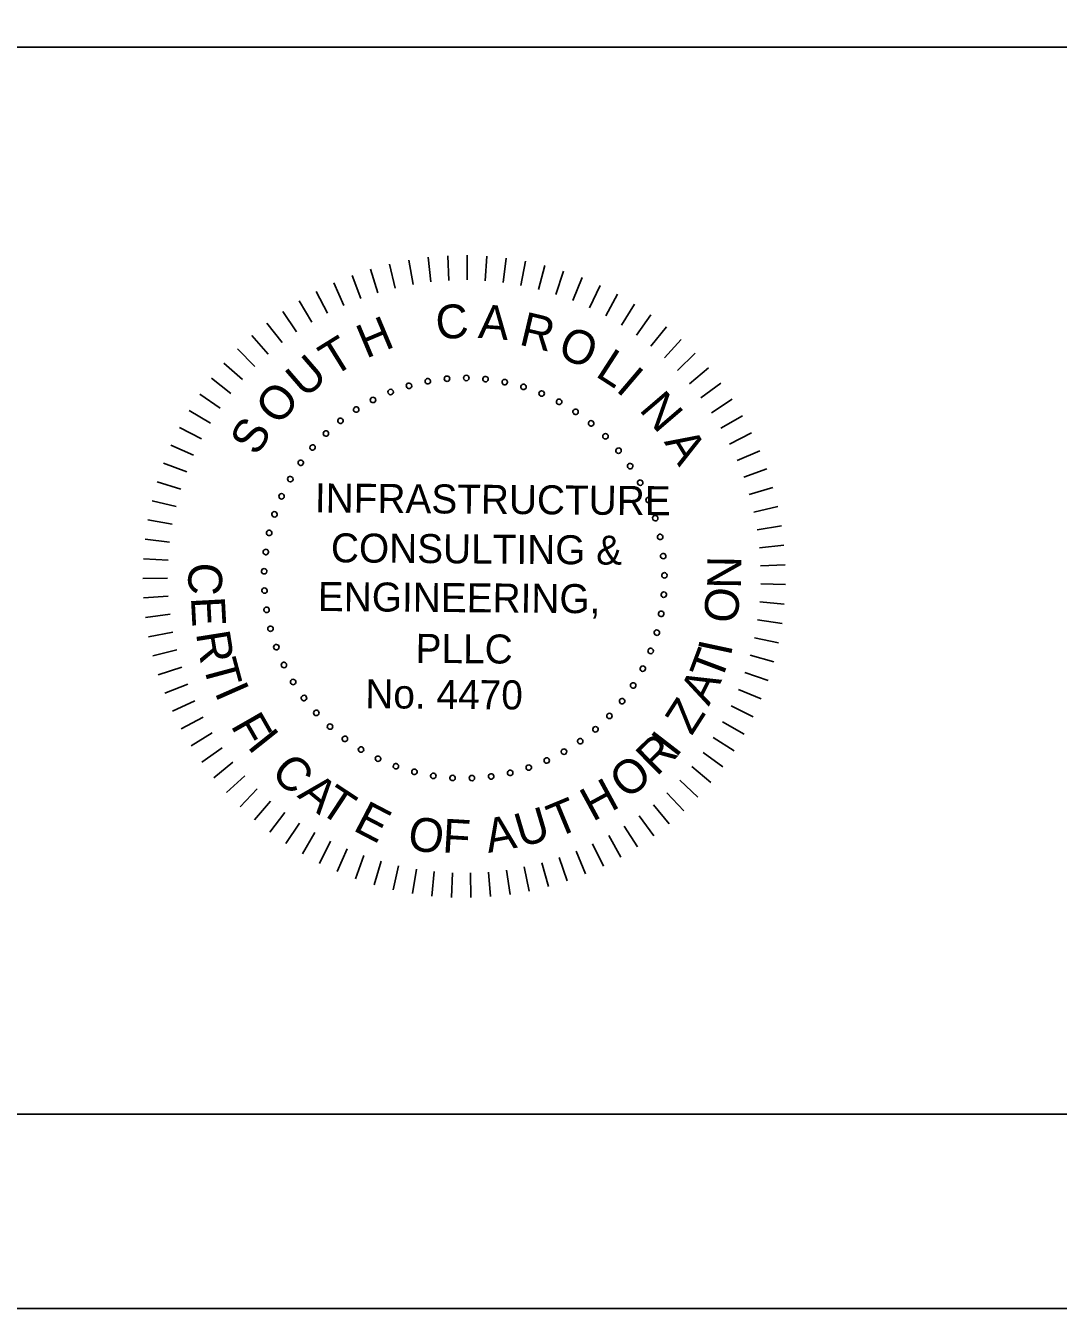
# Model space of a CAD drawing. Extents: x -125.5 to -89.4, y -5.1 to 16.9.
# Drawn here: x -100.33 to -97.669, y -5.066 to -1.761 of the extents above; entities that cross this region are included whole.
import ezdxf

# ---------------------------------------------------------------- set-up
doc = ezdxf.new("R2010")
doc.units = 0
for name, color, linetype in [('BR_BORDER LINES', 7, 'Continuous'), ('BR_TEXT', 7, 'Continuous'), ('Level 31', 7, 'Continuous')]:
    doc.layers.add(name, color=color, linetype=linetype)

msp = doc.modelspace()

# ---------------------------------------------------------------- linework, layer by layer
at = {"layer": 'BR_BORDER LINES'}
for p, q in [((-102.8989, -1.8161), (-97.5337, -1.8161)), ((-123.6994, -4.5662), (-90.0334, -4.5662))]:
    msp.add_line(p, q, dxfattribs=at)
at = {"layer": 'BR_TEXT'}
for p, q in [((-99.3925, -2.3754), (-99.3776, -2.4373)), ((-99.343, -2.3651), (-99.332, -2.4278)), ((-99.2931, -2.3579), (-99.2858, -2.4212)), ((-99.2427, -2.3538), (-99.2394, -2.4174)), ((-99.1923, -2.3527), (-99.1928, -2.4164)), ((-99.1418, -2.3548), (-99.1462, -2.4183)), ((-99.0916, -2.3599), (-99.0999, -2.423)), ((-99.0418, -2.368), (-99.0539, -2.4305)), ((-98.9925, -2.3792), (-99.0084, -2.4408)), ((-99.489, -2.4048), (-99.4667, -2.4644)), ((-99.4412, -2.3886), (-99.4226, -2.4495)), ((-98.9441, -2.3933), (-98.9637, -2.4539)), ((-98.8966, -2.4104), (-98.9199, -2.4696)), ((-99.5813, -2.4457), (-99.5519, -2.5022)), ((-99.5358, -2.4238), (-99.5099, -2.482)), ((-98.8502, -2.4303), (-98.877, -2.488)), ((-99.6253, -2.4703), (-99.5926, -2.5249)), ((-98.8051, -2.453), (-98.8354, -2.509)), ((-98.7615, -2.4785), (-98.7952, -2.5325)), ((-99.6678, -2.4975), (-99.6318, -2.55)), ((-98.7195, -2.5065), (-98.7564, -2.5584)), ((-99.7086, -2.5273), (-99.6694, -2.5775)), ((-98.6793, -2.5371), (-98.7193, -2.5866)), ((-99.7475, -2.5595), (-99.7053, -2.6072)), ((-98.6411, -2.57), (-98.684, -2.617)), ((-99.7843, -2.5941), (-99.7393, -2.6391)), ((-98.6049, -2.6052), (-98.6506, -2.6495)), ((-99.819, -2.6308), (-99.7713, -2.673)), ((-98.571, -2.6426), (-98.6193, -2.684)), ((-99.8513, -2.6695), (-99.8012, -2.7087)), ((-98.5393, -2.6819), (-98.5901, -2.7204)), ((-99.8813, -2.7102), (-99.8288, -2.7463)), ((-98.5102, -2.7232), (-98.5632, -2.7584)), ((-99.9087, -2.7526), (-99.8541, -2.7854)), ((-98.4836, -2.7661), (-98.5387, -2.798)), ((-99.9334, -2.7965), (-99.877, -2.826)), ((-99.9555, -2.842), (-99.8973, -2.8679)), ((-98.4597, -2.8105), (-98.5166, -2.839)), ((-98.4385, -2.8563), (-98.497, -2.8813)), ((-99.9747, -2.8886), (-99.9151, -2.911)), ((-98.4202, -2.9034), (-98.4801, -2.9248)), ((-99.991, -2.9364), (-99.9302, -2.9551)), ((-98.4047, -2.9514), (-98.4659, -2.9691)), ((-100.0044, -2.9851), (-99.9426, -3)), ((-98.3922, -3.0004), (-98.4544, -3.0143)), ((-100.0149, -3.0345), (-99.9522, -3.0456)), ((-98.3828, -3.05), (-98.4456, -3.0601)), ((-100.0222, -3.0844), (-99.959, -3.0917)), ((-98.3763, -3.1), (-98.4397, -3.1063)), ((-100.0266, -3.1347), (-99.963, -3.1382)), ((-98.373, -3.1504), (-98.4366, -3.1528)), ((-100.0278, -3.1852), (-99.9641, -3.1847)), ((-98.3727, -3.2009), (-98.4363, -3.1994)), ((-100.026, -3.2356), (-99.9625, -3.2313)), ((-98.3755, -3.2513), (-98.4389, -3.2459)), ((-100.0211, -3.2859), (-99.9579, -3.2777)), ((-98.3813, -3.3014), (-98.4443, -3.2922)), ((-100.0131, -3.3357), (-99.9506, -3.3237)), ((-98.3902, -3.3511), (-98.4525, -3.3381)), ((-100.0021, -3.385), (-99.9405, -3.3692)), ((-98.4021, -3.4002), (-98.4635, -3.3834)), ((-99.9882, -3.4335), (-99.9276, -3.414)), ((-98.417, -3.4484), (-98.4773, -3.4279)), ((-99.9713, -3.4811), (-99.912, -3.4579)), ((-99.9515, -3.5276), (-99.8937, -3.5008)), ((-98.4348, -3.4957), (-98.4937, -3.4715)), ((-98.4554, -3.5417), (-98.5128, -3.514)), ((-99.929, -3.5727), (-99.8729, -3.5425)), ((-98.4789, -3.5865), (-98.5344, -3.5553)), ((-99.9037, -3.6164), (-99.8496, -3.5828)), ((-98.505, -3.6297), (-98.5585, -3.5952)), ((-99.8758, -3.6585), (-99.8239, -3.6217)), ((-98.5336, -3.6712), (-98.5849, -3.6335)), ((-99.8454, -3.6988), (-99.7958, -3.6589)), ((-99.8126, -3.7372), (-99.7655, -3.6943)), ((-98.5648, -3.7109), (-98.6137, -3.6702)), ((-99.7775, -3.7735), (-99.7331, -3.7278)), ((-98.5983, -3.7487), (-98.6447, -3.705)), ((-99.7403, -3.8076), (-99.6988, -3.7593)), ((-98.6341, -3.7843), (-98.6777, -3.7379)), ((-99.701, -3.8393), (-99.6626, -3.7886)), ((-98.7118, -3.8487), (-98.7494, -3.7974)), ((-98.672, -3.8177), (-98.7126, -3.7687)), ((-99.6599, -3.8687), (-99.6246, -3.8157)), ((-98.7534, -3.8772), (-98.7879, -3.8237)), ((-99.6171, -3.8954), (-99.5851, -3.8404)), ((-99.5728, -3.9195), (-99.5442, -3.8626)), ((-98.7967, -3.9032), (-98.8278, -3.8476)), ((-99.527, -3.9408), (-99.5019, -3.8823)), ((-99.48, -3.9594), (-99.4586, -3.8994)), ((-98.8877, -3.9469), (-98.9118, -3.888)), ((-98.8416, -3.9264), (-98.8692, -3.8691)), ((-99.432, -3.975), (-99.4143, -3.9138)), ((-99.3832, -3.9876), (-99.3692, -3.9255)), ((-99.0324, -3.991), (-99.0454, -3.9286)), ((-98.9833, -3.9792), (-99.0001, -3.9178)), ((-98.935, -3.9645), (-98.9555, -3.9042)), ((-99.3336, -3.9973), (-99.3234, -3.9344)), ((-99.2836, -4.0039), (-99.2772, -3.9406)), ((-99.2332, -4.0075), (-99.2307, -3.9438)), ((-99.1827, -4.0079), (-99.1841, -3.9443)), ((-99.1323, -4.0053), (-99.1376, -3.9419)), ((-99.0821, -3.9997), (-99.0913, -3.9367))]:
    msp.add_line(p, q, dxfattribs=at)
for centre, start, end in [((-99.2939, -2.6775), 10.6038, 190.6038), ((-99.2939, -2.6775), 190.6038, 10.6038), ((-99.2445, -2.6708), 5.0653, 185.0653), ((-99.2445, -2.6708), 185.0653, 5.0653), ((-99.1947, -2.6689), 359.5268, 179.5268), ((-99.1947, -2.6689), 179.5268, 359.5268), ((-99.145, -2.6718), 173.9884, 353.9884), ((-99.145, -2.6718), 353.9884, 173.9884), ((-99.0957, -2.6795), 348.4499, 168.4499), ((-99.3896, -2.705), 21.6807, 201.6807), ((-99.3896, -2.705), 201.6807, 21.6807), ((-99.3424, -2.6889), 16.1422, 196.1422), ((-99.3424, -2.6889), 196.1422, 16.1422), ((-99.0957, -2.6795), 168.4499, 348.4499), ((-99.0475, -2.6919), 162.9114, 342.9114), ((-99.0475, -2.6919), 342.9114, 162.9114), ((-99.0006, -2.709), 157.373, 337.373), ((-99.0006, -2.709), 337.373, 157.373), ((-99.435, -2.7255), 27.2191, 207.2191), ((-99.435, -2.7255), 207.2191, 27.2191), ((-98.9557, -2.7304), 151.8345, 331.8345), ((-98.9557, -2.7304), 331.8345, 151.8345), ((-99.5188, -2.7792), 38.2961, 218.2961), ((-99.5188, -2.7792), 218.2961, 38.2961), ((-99.4782, -2.7503), 32.7576, 212.7576), ((-99.4782, -2.7503), 212.7576, 32.7576), ((-98.913, -2.7561), 146.2961, 326.2961), ((-98.913, -2.7561), 326.2961, 146.2961), ((-99.5564, -2.8119), 43.8345, 223.8345), ((-99.5564, -2.8119), 223.8345, 43.8345), ((-98.873, -2.7858), 140.7576, 320.7576), ((-98.873, -2.7858), 320.7576, 140.7576), ((-99.5907, -2.848), 49.373, 229.373), ((-98.836, -2.8192), 135.2191, 315.2191), ((-98.836, -2.8192), 315.2191, 135.2191), ((-99.5907, -2.848), 229.373, 49.373), ((-98.8024, -2.8561), 129.6807, 309.6807), ((-98.8024, -2.8561), 309.6807, 129.6807), ((-99.6214, -2.8873), 54.9114, 234.9114), ((-99.6214, -2.8873), 234.9114, 54.9114), ((-98.7726, -2.896), 124.1422, 304.1422), ((-98.7726, -2.896), 304.1422, 124.1422), ((-99.6481, -2.9293), 60.4499, 240.4499), ((-99.6481, -2.9293), 240.4499, 60.4499), ((-98.7467, -2.9386), 118.6038, 298.6038), ((-98.7467, -2.9386), 298.6038, 118.6038), ((-99.6706, -2.9738), 65.9884, 245.9884), ((-99.6706, -2.9738), 245.9884, 65.9884), ((-98.7251, -2.9835), 113.0653, 293.0653), ((-98.7251, -2.9835), 293.0653, 113.0653), ((-99.6888, -3.0202), 71.5268, 251.5268), ((-99.6888, -3.0202), 251.5268, 71.5268), ((-98.7079, -3.0302), 107.5268, 287.5268), ((-98.7079, -3.0302), 287.5268, 107.5268), ((-99.7024, -3.0681), 77.0653, 257.0653), ((-99.7024, -3.0681), 257.0653, 77.0653), ((-98.6953, -3.0785), 101.9884, 281.9884), ((-98.6953, -3.0785), 281.9884, 101.9884), ((-99.7113, -3.1172), 82.6038, 262.6038), ((-99.7113, -3.1172), 262.6038, 82.6038), ((-98.6874, -3.1277), 96.4499, 276.4499), ((-98.6874, -3.1277), 276.4499, 96.4499), ((-99.7154, -3.1668), 88.1422, 268.1422), ((-99.7154, -3.1668), 268.1422, 88.1422), ((-98.6843, -3.1774), 90.9114, 270.9114), ((-98.6843, -3.1774), 270.9114, 90.9114), ((-99.7147, -3.2167), 93.6807, 273.6807), ((-99.7147, -3.2167), 273.6807, 93.6807), ((-98.686, -3.2272), 85.373, 265.373), ((-98.686, -3.2272), 265.373, 85.373), ((-99.7092, -3.2662), 99.2191, 279.2191), ((-99.7092, -3.2662), 279.2191, 99.2191), ((-98.6926, -3.2766), 79.8345, 259.8345), ((-98.6926, -3.2766), 259.8345, 79.8345), ((-99.6989, -3.3149), 104.7576, 284.7576), ((-99.6989, -3.3149), 284.7576, 104.7576), ((-98.7038, -3.3251), 74.2961, 254.2961), ((-98.7038, -3.3251), 254.2961, 74.2961), ((-99.684, -3.3625), 110.2961, 290.2961), ((-99.684, -3.3625), 290.2961, 110.2961), ((-98.7197, -3.3724), 68.7576, 248.7576), ((-98.7197, -3.3724), 248.7576, 68.7576), ((-99.6646, -3.4084), 115.8345, 295.8345), ((-99.6646, -3.4084), 295.8345, 115.8345), ((-98.7401, -3.4178), 63.2191, 243.2191), ((-98.7401, -3.4178), 243.2191, 63.2191), ((-99.6408, -3.4522), 121.373, 301.373), ((-99.6408, -3.4522), 301.373, 121.373), ((-98.7647, -3.4611), 57.6807, 237.6807), ((-98.7647, -3.4611), 237.6807, 57.6807), ((-99.6129, -3.4935), 126.9114, 306.9114), ((-99.6129, -3.4935), 306.9114, 126.9114), ((-98.7934, -3.5019), 52.1422, 232.1422), ((-98.7934, -3.5019), 232.1422, 52.1422), ((-99.5812, -3.5319), 132.4499, 312.4499), ((-99.5812, -3.5319), 312.4499, 132.4499), ((-98.826, -3.5396), 46.6038, 226.6038), ((-98.826, -3.5396), 226.6038, 46.6038), ((-99.5459, -3.5671), 137.9884, 317.9884), ((-99.5459, -3.5671), 317.9884, 137.9884), ((-98.862, -3.5741), 41.0653, 221.0653), ((-99.5074, -3.5987), 143.5268, 323.5268), ((-99.5074, -3.5987), 323.5268, 143.5268), ((-98.9012, -3.6049), 35.5268, 215.5268), ((-98.9012, -3.6049), 215.5268, 35.5268), ((-98.862, -3.5741), 221.0653, 41.0653), ((-99.466, -3.6264), 149.0653, 329.0653), ((-99.466, -3.6264), 329.0653, 149.0653), ((-98.9431, -3.6317), 29.9884, 209.9884), ((-98.9431, -3.6317), 209.9884, 29.9884), ((-99.4221, -3.65), 154.6038, 334.6038), ((-99.4221, -3.65), 334.6038, 154.6038), ((-99.3761, -3.6693), 160.1422, 340.1422), ((-99.3761, -3.6693), 340.1422, 160.1422), ((-99.0338, -3.6728), 18.9114, 198.9114), ((-98.9875, -3.6545), 24.4499, 204.4499), ((-98.9875, -3.6545), 204.4499, 24.4499), ((-99.3285, -3.684), 165.6807, 345.6807), ((-99.3285, -3.684), 345.6807, 165.6807), ((-99.2797, -3.6941), 351.2191, 171.2191), ((-99.2797, -3.6941), 171.2191, 351.2191), ((-99.2302, -3.6994), 356.7576, 176.7576), ((-99.2302, -3.6994), 176.7576, 356.7576), ((-99.1803, -3.6999), 2.2961, 182.2961), ((-99.1803, -3.6999), 182.2961, 2.2961), ((-99.1307, -3.6956), 7.8345, 187.8345), ((-99.1307, -3.6956), 187.8345, 7.8345), ((-99.0817, -3.6865), 13.373, 193.373), ((-99.0817, -3.6865), 193.373, 13.373), ((-99.0338, -3.6728), 198.9114, 18.9114)]:
    msp.add_arc(centre, 0.00701, start, end, dxfattribs=at)
at = {"layer": 'Level 31'}
msp.add_lwpolyline([(-125.5328, -5.0661), (-89.5328, -5.0661), (-89.5328, 16.9339), (-125.5328, 16.9339)], close=True, dxfattribs=at)

# ---------------------------------------------------------------- texts
at = {"layer": 'BR_TEXT'}
for s, height, rotation, p in [('C', 0.0872, 4.7281, (-99.2702, -2.5703)), ('H', 0.0872, 22.7882, (-99.453, -2.6197)), ('A', 0.0872, 355.6981, (-99.1657, -2.5654)), ('R', 0.0872, 346.6681, (-99.0615, -2.5824)), ('O', 0.0872, 337.638, (-98.9637, -2.6122)), ('T', 0.0872, 31.8182, (-99.5379, -2.6674)), ('U', 0.0872, 40.8482, (-99.6112, -2.7235)), ('L', 0.0872, 327.108, (-98.8649, -2.6626)), ('I', 0.0872, 319.578, (-98.8123, -2.7005)), ('O', 0.0872, 49.8782, (-99.6782, -2.7945)), ('N', 0.0872, 310.548, (-98.7515, -2.7512)), ('S', 0.0872, 58.9083, (-99.7336, -2.8727)), ('A', 0.0872, 301.5179, (-98.6864, -2.8336)), ('INFRASTRUCTURE', 0.074771, 359.5268, (-99.585, -3.0152)), ('CONSULTING &', 0.074771, 359.5268, (-99.5437, -3.1438)), ('N', 0.0872, 89.2085, (-98.4872, -3.2124)), ('C', 0.0872, 267.025, (-99.9086, -3.1426)), ('ENGINEERING,', 0.074771, 359.5268, (-99.5773, -3.2693)), ('O', 0.0872, 83.2085, (-98.4982, -3.3038)), ('E', 0.0872, 273.025, (-99.9042, -3.2342)), ('R', 0.0872, 279.025, (-99.8914, -3.3265)), ('PLLC', 0.07477, 359.5268, (-99.3256, -3.4028)), ('T', 0.0872, 69.3954, (-98.5394, -3.4556)), ('I', 0.0872, 77.9093, (-98.5137, -3.3881)), ('T', 0.0872, 285.025, (-99.874, -3.4053)), ('A', 0.0872, 63.3954, (-98.5702, -3.516)), ('I', 0.0872, 293.7713, (-99.8443, -3.4784)), ('No. 4470', 0.07477, 359.5268, (-99.4551, -3.5197)), ('Z', 0.0872, 57.3954, (-98.6141, -3.5923)), ('F', 0.0872, 299.7713, (-99.8031, -3.5644)), ('I', 0.0872, 308.5268, (-99.761, -3.6183)), ('R', 0.0872, 44.5268, (-98.7045, -3.6973)), ('I', 0.0872, 52.3339, (-98.6551, -3.65)), ('C', 0.0872, 314.5268, (-99.7017, -3.6884)), ('O', 0.0872, 38.5268, (-98.7811, -3.7572)), ('A', 0.0872, 320.5268, (-99.6325, -3.747)), ('H', 0.0872, 28.5268, (-98.8692, -3.8132)), ('T', 0.0872, 326.5268, (-99.5781, -3.7855)), ('E', 0.0872, 332.5268, (-99.4895, -3.8332)), ('T', 0.0872, 22.5268, (-98.9624, -3.855)), ('O', 0.0872, 350.5268, (-99.3494, -3.8821)), ('A', 0.0872, 10.5268, (-99.138, -3.8929)), ('U', 0.0872, 16.5268, (-99.0541, -3.8794)), ('F', 0.0872, 356.5268, (-99.2579, -3.8912))]:
    msp.add_text(s, height=height, rotation=rotation, dxfattribs=at).set_placement(p)

doc.saveas('drawing.dxf')
